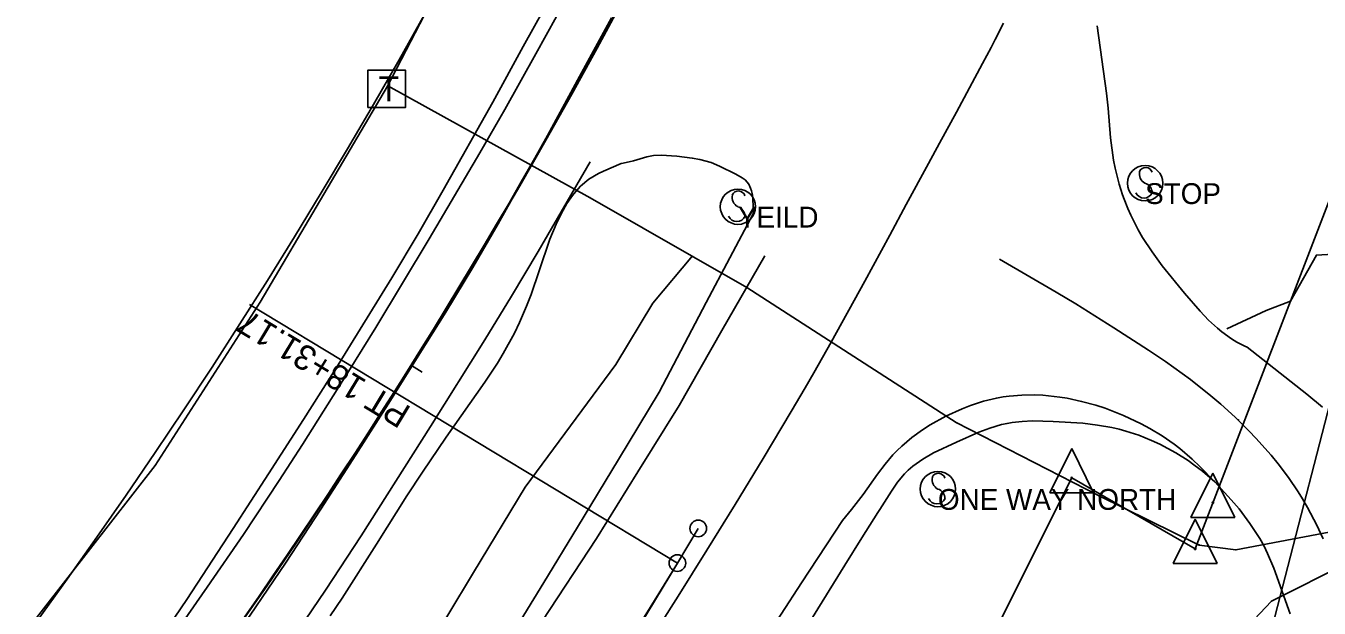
# Model space of a CAD drawing. Extents: x 1674300 to 1677920, y 225056 to 231852.
# Drawn here: x 1677063.6 to 1677374.1, y 228161.2 to 228300.9 of the extents above; entities that cross this region are included whole.
import ezdxf

# ---------------------------------------------------------------- set-up
doc = ezdxf.new("R2010")
doc.units = 0
for name, color, linetype in [('R_Horz Alg', 7, 'Continuous'), ('R_Horz Alg Annot', 7, 'Continuous'), ('S_DITCHLINE', 7, 'Continuous'), ('S_EDGE_PAVEMENT', 7, 'Continuous'), ('S_ELECTRIC_UTILITIES', 7, 'Continuous'), ('S_EXIST_ROW', 7, 'Continuous'), ('S_EXISTING_ALIGNMENT', 7, 'Continuous'), ('S_FIBER_OPTIC_CABLE', 7, 'Continuous'), ('S_GRAVEL_ROAD', 7, 'Continuous'), ('S_MSC_PT_SYM', 7, 'Continuous'), ('S_PAVEMENT_CROWN', 7, 'Continuous'), ('S_SHOULDER', 7, 'Continuous'), ('S_SIGN', 7, 'Continuous'), ('S_SIGN_ANNOT', 7, 'Continuous'), ('S_TELEPHONE_UTILITIES', 7, 'Continuous'), ('S_UTL_PT_SYM', 7, 'Continuous')]:
    doc.layers.add(name, color=color, linetype=linetype)

msp = doc.modelspace()

# ---------------------------------------------------------------- linework, layer by layer
at = {"layer": 'R_Horz Alg'}
msp.add_line((1677220, 228172.01), (1677225.02, 228180.32), dxfattribs=at)
for centre, radius, end in [((1675928.16, 228988.54), 1449, 0.80558), ((1676402.48, 228665.51), 954.93, 328.88259)]:
    msp.add_arc(centre, radius, 296.0624, end, dxfattribs=at)
at = {"layer": 'R_Horz Alg Annot'}
msp.add_line((1677074.66, 227931.25), (1677220, 228172.01), dxfattribs=at)
for points in [[(1677220, 228172.01), (1677117.27, 228234.03)], [(1677158.73, 228217.83), (1677156.19, 228219.42)]]:
    msp.add_lwpolyline(points, dxfattribs=at)
for centre in [(1677225.02, 228180.32), (1677220, 228172.01)]:
    msp.add_circle(centre, 2, dxfattribs=at)
at = {"layer": 'S_DITCHLINE'}
msp.add_lwpolyline([(1677139.76, 228123.95), (1677153.43, 228142.29), (1677158.71, 228149.29), (1677171.09, 228169.75), (1677183.47, 228190.22), (1677194.37, 228204.93), (1677205.27, 228219.64), (1677214.14, 228234.4), (1677223.67, 228245.72)], dxfattribs=at)
at = {"layer": 'S_EDGE_PAVEMENT'}
for points in [[(1677059.75, 228102.25), (1677066.21, 228110.42), (1677075.74, 228122.78), (1677080.32, 228128.89), (1677089.37, 228141.18), (1677101.3, 228157.81), (1677107.16, 228166.19), (1677115.82, 228178.85), (1677124.4, 228191.78), (1677130.03, 228200.46), (1677141.07, 228217.94), (1677147.6, 228228.52), (1677160.44, 228249.79), (1677172.59, 228270.43), (1677178.55, 228280.82), (1677186.05, 228294.21), (1677190.97, 228303.18)], [(1677374.9, 228209.39), (1677371.13, 228212.53), (1677356.79, 228223.79), (1677356.22, 228224.05), (1677354.29, 228225.04), (1677353.07, 228225.78), (1677350.75, 228227.46), (1677349.65, 228228.37), (1677347.54, 228230.33), (1677345.53, 228232.42), (1677341.72, 228236.81), (1677336.42, 228243.33), (1677333.96, 228246.68), (1677331.69, 228250.16), (1677330.64, 228251.96), (1677328.85, 228255.49), (1677328.14, 228257.11), (1677327.27, 228259.3), (1677326.87, 228260.41), (1677326.06, 228262.94), (1677325.08, 228266.78), (1677324.71, 228268.72), (1677324.02, 228274.02), (1677323.4, 228281.16), (1677322.99, 228284.76), (1677320.78, 228300.93)], [(1677054.49, 228057.98), (1677064.77, 228070.36), (1677074.88, 228082.91), (1677081.54, 228091.34), (1677094.67, 228108.34), (1677104.72, 228121.64), (1677109.67, 228128.34), (1677118.48, 228140.59), (1677124.25, 228148.83), (1677135.54, 228165.49), (1677144.07, 228178.51), (1677152.42, 228191.65), (1677160.77, 228204.79), (1677173.76, 228225.6), (1677180.15, 228236.06), (1677186.55, 228246.75), (1677199.05, 228268.29)], [(1677050.47, 227960.42), (1677064.47, 227975.57), (1677071.28, 227983.29), (1677077.87, 227991.2), (1677081.05, 227995.24), (1677086, 228001.89), (1677089.18, 228006.41), (1677095.28, 228015.66), (1677103.13, 228028.07), (1677110.98, 228040.48), (1677123.03, 228059.15), (1677135.07, 228077.82), (1677142.69, 228089.53), (1677150.3, 228101.23), (1677162.42, 228119.68), (1677174.53, 228138.13), (1677187.58, 228158.03), (1677200.63, 228177.93), (1677210.53, 228193.87), (1677220.43, 228209.81), (1677230.72, 228227.78), (1677241.01, 228245.75)], [(1677240.04, 228152.19), (1677249.84, 228167.22), (1677259.63, 228182.24), (1677260.35, 228183.07), (1677261.84, 228184.85), (1677264.58, 228188.49), (1677268.07, 228193.36), (1677269.86, 228195.7), (1677271.77, 228197.94), (1677272.79, 228199.01), (1677273.91, 228200.09), (1677276.31, 228202.13), (1677278.89, 228203.99), (1677280.68, 228205.14), (1677284.42, 228207.22), (1677288.37, 228209.05), (1677290.38, 228209.83), (1677293.46, 228210.84), (1677296.59, 228211.6), (1677298.18, 228211.89), (1677299.68, 228212.09), (1677302.7, 228212.33), (1677305.74, 228212.36), (1677307.76, 228212.26), (1677311.8, 228211.83), (1677313.55, 228211.55), (1677317.04, 228210.81), (1677320.46, 228209.87), (1677322.72, 228209.14), (1677327.14, 228207.42), (1677331.36, 228205.43), (1677333.41, 228204.32), (1677336.4, 228202.51), (1677339.26, 228200.52), (1677340.64, 228199.47), (1677343.56, 228196.97), (1677345.43, 228195.21), (1677349.05, 228191.52), (1677352.97, 228187.21), (1677354.84, 228184.98), (1677357.47, 228181.52), (1677359.81, 228177.9), (1677360.85, 228176.02), (1677361.69, 228174.31), (1677363.19, 228170.78), (1677367.12, 228159.82)]]:
    msp.add_lwpolyline(points, dxfattribs=at)
at = {"layer": 'S_ELECTRIC_UTILITIES'}
msp.add_line((1677343.16, 228080.48), (1677425.49, 228399.8), dxfattribs=at)
at = {"layer": 'S_EXIST_ROW'}
for p, q in [((1677344.31, 228175.41), (1677424.97, 228385.14)), ((1677314.71, 228199.51), (1677309.42, 228188.87)), ((1677314.71, 228199.51), (1677319.94, 228188.87)), ((1677264.8, 228093.13), (1677314.69, 228192.42)), ((1677314.69, 228192.42), (1677314.69, 228192.42)), ((1677314.69, 228192.42), (1677344.31, 228175.41)), ((1677348.59, 228193.59), (1677343.3, 228182.96)), ((1677348.59, 228193.59), (1677353.82, 228182.96)), ((1677309.42, 228188.87), (1677319.94, 228188.87)), ((1677348.57, 228186.5), (1677348.57, 228186.5)), ((1677344.33, 228182.5), (1677339.04, 228171.87)), ((1677343.3, 228182.96), (1677353.82, 228182.96)), ((1677344.33, 228182.5), (1677349.56, 228171.87)), ((1677344.31, 228175.41), (1677344.31, 228175.41)), ((1677339.04, 228171.87), (1677349.56, 228171.87))]:
    msp.add_line(p, q, dxfattribs=at)
for centre, radius in [((1677314.69, 228192.42), 0.18), ((1677314.69, 228192.42), 0.09), ((1677348.57, 228186.5), 0.18), ((1677348.57, 228186.5), 0.09), ((1677344.31, 228175.41), 0.18), ((1677344.31, 228175.41), 0.09)]:
    msp.add_circle(centre, radius, dxfattribs=at)
msp.add_arc((1675926.71, 228989.39), 1410.53, 295.94359, 0.85682, dxfattribs=at)
at = {"layer": 'S_EXISTING_ALIGNMENT'}
msp.add_arc((1675926.71, 228989.39), 1450.53, 315.98862, 345.81316, dxfattribs=at)
at = {"layer": 'S_FIBER_OPTIC_CABLE'}
for p, q in [((1677150.44, 228286.49), (1677167.35, 228319.14)), ((1677119.84, 228234.61), (1677150.44, 228286.49)), ((1677150.46, 228286.55), (1677199.06, 228259.69)), ((1677199.06, 228259.69), (1677236.65, 228238.11)), ((1677236.65, 228238.11), (1677286.95, 228205.7)), ((1677094.67, 228195.4), (1677119.84, 228234.61)), ((1677286.95, 228205.7), (1677321.23, 228188.13)), ((1677055.89, 228145.71), (1677094.67, 228195.4)), ((1677321.23, 228188.13), (1677345.29, 228176.33)), ((1677354.08, 228175.16), (1677393.7, 228182.74)), ((1677362.65, 228162.87), (1677395.47, 228179.35)), ((1677345.29, 228176.33), (1677354.08, 228175.16)), ((1677342.55, 228141.77), (1677362.65, 228162.87))]:
    msp.add_line(p, q, dxfattribs=at)
at = {"layer": 'S_GRAVEL_ROAD'}
msp.add_lwpolyline([(1677391.86, 228178.22), (1677389.92, 228197.38), (1677387.97, 228216.53), (1677387.22, 228231.6), (1677386.46, 228246.68), (1677373.41, 228245.91), (1677367.22, 228234.89), (1677361.37, 228232.62), (1677351.91, 228228.25)], dxfattribs=at)
at = {"layer": 'S_MSC_PT_SYM'}
msp.add_lwpolyline([(1677354.75, 228206.33), (1677354.75, 228206.38), (1677354.75, 228206.33), (1677354.7, 228206.33), (1677354.75, 228206.33), (1677354.75, 228206.28), (1677354.75, 228206.33), (1677354.8, 228206.33)], dxfattribs=at)
at = {"layer": 'S_PAVEMENT_CROWN'}
for points in [[(1677055.98, 228078.31), (1677065.91, 228090.56), (1677072.44, 228098.8), (1677085.3, 228115.44), (1677099.96, 228135.04), (1677111.69, 228151.31), (1677117.43, 228159.53), (1677125.9, 228171.96), (1677134.43, 228184.91), (1677142.78, 228197.98), (1677151.13, 228211.05), (1677157.77, 228221.65), (1677164.42, 228232.25), (1677170.89, 228242.95), (1677176.98, 228253.45), (1677188.82, 228274.65), (1677196.51, 228288.75), (1677204.2, 228302.85)], [(1677211.52, 228150.46), (1677220.23, 228164.08), (1677227.05, 228175.06), (1677233.86, 228186.03), (1677240.57, 228197.07), (1677247.35, 228208.36), (1677250.69, 228214.03), (1677252.78, 228217.67), (1677256.92, 228224.98), (1677265, 228239.68), (1677269, 228247.04), (1677270.99, 228250.71), (1677274.97, 228258.06), (1677280.3, 228267.86), (1677282.97, 228272.78), (1677287, 228280.19), (1677293.29, 228291.86), (1677295.33, 228295.75), (1677296.33, 228297.69), (1677298.28, 228301.57)], [(1677375.04, 228177.84), (1677373.54, 228181.1), (1677371.31, 228185.34), (1677370.1, 228187.4), (1677369.02, 228189.13), (1677366.71, 228192.52), (1677364.25, 228195.78), (1677362.53, 228197.9), (1677358.91, 228201.99), (1677357.28, 228203.69), (1677353.94, 228206.98), (1677350.46, 228210.13), (1677348.08, 228212.16), (1677343.18, 228216.04), (1677337.18, 228220.34), (1677333.09, 228223.09), (1677324.81, 228228.42), (1677315.63, 228234.2), (1677310.97, 228236.99), (1677297.32, 228244.96)]]:
    msp.add_lwpolyline(points, dxfattribs=at)
at = {"layer": 'S_SHOULDER'}
for points in [[(1677060.59, 228107.91), (1677073.75, 228124.38), (1677083.08, 228136.31), (1677087.63, 228142.35), (1677090.64, 228146.47), (1677096.51, 228154.8), (1677102.23, 228163.25), (1677113.4, 228180.31), (1677121.81, 228193.39), (1677130.22, 228206.46), (1677138.54, 228219.58), (1677151.45, 228240.47), (1677157.74, 228251), (1677163.82, 228261.48), (1677175.7, 228282.6), (1677183.02, 228295.95), (1677190.34, 228309.3)], [(1677136.66, 228159.31), (1677139.51, 228163.58), (1677147.8, 228176.56), (1677155.09, 228188.13), (1677158.79, 228193.84), (1677164.47, 228202.24), (1677173.82, 228215.42), (1677176.79, 228219.97), (1677178.21, 228222.31), (1677180.88, 228227.17), (1677182.12, 228229.7), (1677183.82, 228233.66), (1677184.87, 228236.44), (1677186.8, 228242.17), (1677189.4, 228249.75), (1677190.87, 228253.35), (1677192.55, 228256.71), (1677193.48, 228258.28), (1677194.85, 228260.23), (1677195.6, 228261.14), (1677196.79, 228262.42), (1677198.78, 228264.11), (1677201.04, 228265.51), (1677202.27, 228266.09), (1677206.5, 228267.87), (1677206.98, 228267.95), (1677209.47, 228268.53), (1677212.66, 228269.48), (1677214.27, 228269.8), (1677216.11, 228269.91), (1677219.85, 228269.64), (1677223.57, 228269.19), (1677225.39, 228268.87), (1677228.09, 228268.14), (1677230.16, 228267.29), (1677234.08, 228265.32), (1677235.59, 228264.48), (1677236.26, 228263.96), (1677237.14, 228262.9), (1677237.6, 228261.94), (1677237.78, 228261.36), (1677238.01, 228260.36), (1677238.24, 228257.89), (1677238.29, 228255.7), (1677238.29, 228255.98), (1677238.29, 228256.03)], [(1677062.58, 227984.81), (1677066.67, 227990.02), (1677074.69, 228000.56), (1677085.1, 228014.86), (1677091.88, 228024.5), (1677105.21, 228043.97), (1677113.63, 228056.4), (1677122.05, 228068.83), (1677130.61, 228081.17), (1677138.55, 228092.33), (1677146.5, 228103.49), (1677155.05, 228115.85), (1677160.65, 228124.16), (1677171.59, 228140.95), (1677179.87, 228154.1), (1677187.96, 228167.37), (1677196.06, 228180.63), (1677205.85, 228196.84), (1677215.64, 228213.05), (1677226.95, 228234.53), (1677238.26, 228256)], [(1677252.02, 228158.3), (1677260.19, 228171.46), (1677264.29, 228178.03), (1677268.17, 228184.17), (1677268.6, 228184.84), (1677271.38, 228189.27), (1677272.87, 228191.4), (1677274.51, 228193.38), (1677275.4, 228194.29), (1677276.5, 228195.26), (1677278.91, 228196.97), (1677281.51, 228198.45), (1677287.02, 228201.04), (1677292.36, 228203.39), (1677295.05, 228204.41), (1677297.78, 228205.22), (1677299.17, 228205.53), (1677300.36, 228205.73), (1677302.79, 228205.99), (1677305.25, 228206.1), (1677310.22, 228206.01), (1677317.34, 228205.56), (1677320.86, 228205.13), (1677324.34, 228204.51), (1677326.07, 228204.11), (1677327.65, 228203.68), (1677330.78, 228202.66), (1677333.84, 228201.43), (1677335.84, 228200.5), (1677339.71, 228198.42), (1677342.61, 228196.59), (1677344.01, 228195.6), (1677346.07, 228194.04), (1677349.04, 228191.5)]]:
    msp.add_lwpolyline(points, dxfattribs=at)
at = {"layer": 'S_SIGN'}
for centre in [(1677332.3, 228263.17), (1677234.55, 228257.53), (1677282.56, 228189.77)]:
    msp.add_circle(centre, 4.24, dxfattribs=at)
for centre, radius, start, end in [((1677333.46, 228265.42), 2.55, 167.1196, 241.9813), ((1677332.42, 228265.32), 1.62, 16.5258, 156.8957), ((1677331.6, 228260.89), 2.38, 358.6529, 73.7063), ((1677235.71, 228259.79), 2.55, 167.1196, 241.9813), ((1677234.67, 228259.69), 1.62, 16.5258, 156.8957), ((1677332.04, 228261.77), 2.17, 204.641, 335.359), ((1677233.84, 228255.25), 2.38, 358.6529, 73.7063), ((1677234.28, 228256.13), 2.17, 204.641, 335.359), ((1677283.72, 228192.02), 2.55, 167.1196, 241.9813), ((1677282.68, 228191.92), 1.62, 16.5258, 156.8957), ((1677281.86, 228187.49), 2.38, 358.6529, 73.7063), ((1677282.3, 228188.37), 2.17, 204.641, 335.359)]:
    msp.add_arc(centre, radius, start, end, dxfattribs=at)
at = {"layer": 'S_TELEPHONE_UTILITIES'}
msp.add_lwpolyline([(1677145.71, 228281.32), (1677145.71, 228290.32), (1677154.71, 228290.32), (1677154.71, 228281.32)], close=True, dxfattribs=at)
at = {"layer": 'S_UTL_PT_SYM'}
for points in [[(1677150.44, 228286.49), (1677150.44, 228286.54), (1677150.44, 228286.49), (1677150.39, 228286.49), (1677150.44, 228286.49), (1677150.44, 228286.44), (1677150.44, 228286.49), (1677150.49, 228286.49)], [(1677150.46, 228286.55), (1677150.46, 228286.6), (1677150.46, 228286.55), (1677150.41, 228286.55), (1677150.46, 228286.55), (1677150.46, 228286.5), (1677150.46, 228286.55), (1677150.51, 228286.55)], [(1677199.06, 228259.69), (1677199.06, 228259.74), (1677199.06, 228259.69), (1677199.01, 228259.69), (1677199.06, 228259.69), (1677199.06, 228259.64), (1677199.06, 228259.69), (1677199.11, 228259.69)], [(1677236.65, 228238.11), (1677236.65, 228238.16), (1677236.65, 228238.11), (1677236.6, 228238.11), (1677236.65, 228238.11), (1677236.65, 228238.06), (1677236.65, 228238.11), (1677236.7, 228238.11)], [(1677119.84, 228234.61), (1677119.84, 228234.66), (1677119.84, 228234.61), (1677119.79, 228234.61), (1677119.84, 228234.61), (1677119.84, 228234.56), (1677119.84, 228234.61), (1677119.89, 228234.61)], [(1677286.95, 228205.7), (1677286.95, 228205.75), (1677286.95, 228205.7), (1677286.9, 228205.7), (1677286.95, 228205.7), (1677286.95, 228205.65), (1677286.95, 228205.7), (1677287, 228205.7)], [(1677094.67, 228195.4), (1677094.67, 228195.45), (1677094.67, 228195.4), (1677094.62, 228195.4), (1677094.67, 228195.4), (1677094.67, 228195.35), (1677094.67, 228195.4), (1677094.72, 228195.4)], [(1677321.23, 228188.13), (1677321.23, 228188.18), (1677321.23, 228188.13), (1677321.18, 228188.13), (1677321.23, 228188.13), (1677321.23, 228188.08), (1677321.23, 228188.13), (1677321.28, 228188.13)], [(1677345.29, 228176.33), (1677345.29, 228176.38), (1677345.29, 228176.33), (1677345.24, 228176.33), (1677345.29, 228176.33), (1677345.29, 228176.28), (1677345.29, 228176.33), (1677345.34, 228176.33)], [(1677354.08, 228175.16), (1677354.08, 228175.21), (1677354.08, 228175.16), (1677354.03, 228175.16), (1677354.08, 228175.16), (1677354.08, 228175.11), (1677354.08, 228175.16), (1677354.13, 228175.16)], [(1677362.65, 228162.87), (1677362.65, 228162.92), (1677362.65, 228162.87), (1677362.6, 228162.87), (1677362.65, 228162.87), (1677362.65, 228162.82), (1677362.65, 228162.87), (1677362.7, 228162.87)]]:
    msp.add_lwpolyline(points, dxfattribs=at)

# ---------------------------------------------------------------- texts
at = {"layer": 'R_Horz Alg Annot'}
msp.add_text('PT 18+31.17', height=6, rotation=148.8826, dxfattribs=at).set_placement((1677156.39, 228209.24))
at = {"layer": 'S_SIGN_ANNOT'}
for s, p in [('STOP', (1677332.3, 228258.17)), ('YEILD', (1677234.55, 228252.53)), ('ONE WAY NORTH', (1677282.56, 228184.77))]:
    msp.add_text(s, height=5, rotation=360, dxfattribs=at).set_placement(p)
at = {"layer": 'S_TELEPHONE_UTILITIES'}
msp.add_text('T', height=6, rotation=360, dxfattribs=at).set_placement((1677148.27, 228282.82))

doc.saveas('drawing.dxf')
